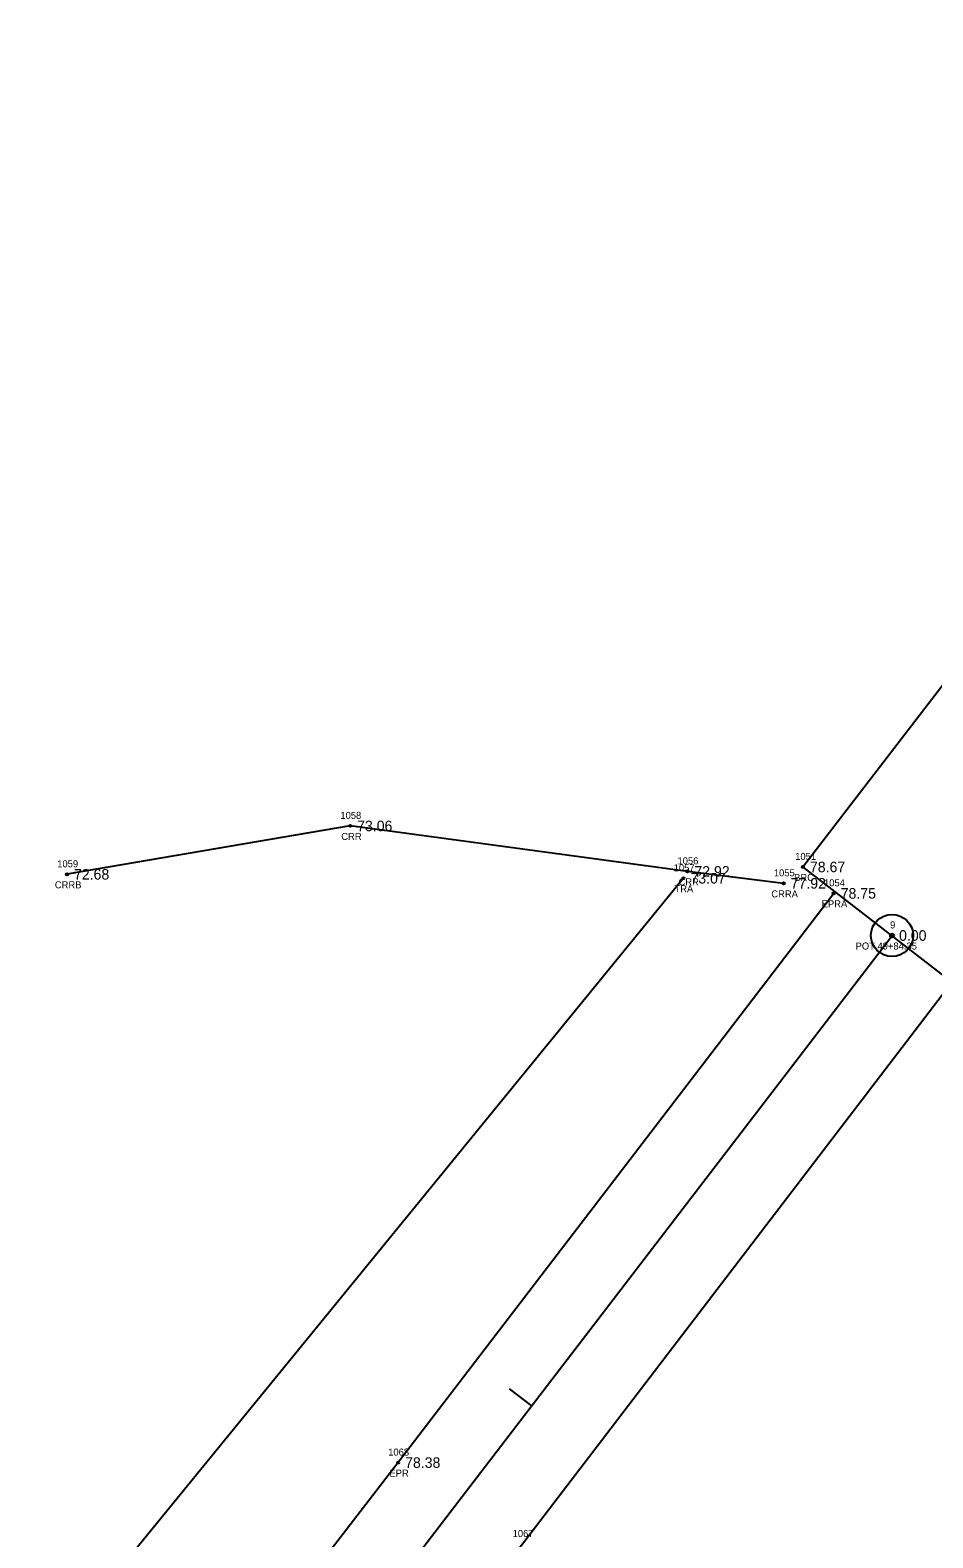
# Model space of a CAD drawing. Extents: x 2505249 to 2506333, y 912937 to 914171.
# Drawn here: x 2505909.6 to 2506038.1, y 913721.3 to 913936 of the extents above; entities that cross this region are included whole.
import ezdxf

# ---------------------------------------------------------------- set-up
doc = ezdxf.new("R2010")
doc.units = 0
for name, color, linetype in [('RD_EX_Bridge', 7, 'Continuous'), ('RD_EX_Bridge_txCode', 7, 'Continuous'), ('RD_EX_H2O', 7, 'Continuous'), ('RD_EX_H2O_txCode', 7, 'Continuous'), ('RD_EX_Road', 7, 'Continuous'), ('RD_EX_Road_txCode', 7, 'Continuous'), ('RD_EX_TX_Bridge_ELEV', 7, 'Continuous'), ('RD_EX_TX_H2O_ELEV', 7, 'Continuous'), ('RD_EX_TX_Road_ELEV', 7, 'Continuous'), ('RD_EX_TX_VEG_ELEV', 7, 'Continuous'), ('RD_EX_VEG', 7, 'Continuous'), ('RD_EX_VEG_txCode', 7, 'Continuous'), ('RD_HC_Cl', 7, 'Continuous'), ('RD_HC_Data', 7, 'Continuous'), ('RD_HC_Data_Tic', 7, 'Continuous'), ('RD_HC_Survey_ELEV', 7, 'Continuous'), ('RD_HC_txCode', 7, 'Continuous'), ('RD_SMD_Locator', 7, 'Continuous')]:
    doc.layers.add(name, color=color, linetype=linetype)

msp = doc.modelspace()

# ---------------------------------------------------------------- linework, layer by layer
at = {"layer": 'RD_EX_Bridge'}
msp.add_lwpolyline([(2506111.24, 913935.99), (2506135.76, 913916.92), (2506044.08, 913798.01), (2506019.65, 913816.86), (2506111.24, 913935.99)], dxfattribs=at)
at = {"layer": 'RD_EX_H2O'}
msp.add_lwpolyline([(2506016.9, 913814.52), (2506003.2, 913816.23), (2505955.18, 913822.7), (2505914.87, 913815.81)], dxfattribs=at)
at = {"layer": 'RD_EX_Road'}
for points in [[(2506024.03, 913813.1), (2505962.01, 913732.06), (2505903.3, 913655.93), (2505840.88, 913574.4), (2505819.41, 913546.54), (2505814.19, 913542.64)], [(2506040.71, 913800.23), (2505979.73, 913720.47), (2505920.44, 913642.61), (2505859.42, 913562.61), (2505835.44, 913531.43), (2505833.77, 913527.25)]]:
    msp.add_lwpolyline(points, dxfattribs=at)
at = {"layer": 'RD_EX_VEG'}
msp.add_lwpolyline([(2506002.64, 913815.25), (2505883.7, 913669.64), (2505827.83, 913593.29), (2505814.43, 913589.15), (2505792.49, 913560.55), (2505725.64, 913468.24), (2505664.37, 913399.09), (2505478.33, 913221), (2505411.99, 913152.19), (2505339.13, 913074.53)], dxfattribs=at)
at = {"layer": 'RD_HC_Cl'}
msp.add_line((2505792.76, 913494.51), (2506032.34, 913807.1), dxfattribs=at)
at = {"layer": 'RD_HC_Data'}
for radius in [3, 0.282]:
    msp.add_circle((2506032.34, 913807.1), radius, dxfattribs=at)
at = {"layer": 'RD_HC_Data_Tic'}
msp.add_line((2505981.03, 913740.15), (2505977.86, 913742.58), dxfattribs=at)
at = {"layer": 'RD_SMD_Locator'}
for centre in [(2505955.18, 913822.7), (2506003.2, 913816.23), (2506019.65, 913816.86), (2505914.87, 913815.81), (2506002.64, 913815.25), (2506016.9, 913814.52), (2506024.03, 913813.1), (2506032.34, 913807.1), (2505962.01, 913732.06)]:
    msp.add_circle(centre, 0.15, dxfattribs=at)

# ---------------------------------------------------------------- texts
at = {"layer": 'RD_EX_Bridge_txCode'}
for s, p in [('1051', (2506018.55, 913817.86)), ('BRC', (2506018.4, 913814.86))]:
    msp.add_text(s, height=1, dxfattribs=at).set_placement(p)
at = {"layer": 'RD_EX_H2O_txCode'}
for s, p in [('1058', (2505953.79, 913823.7)), ('CRR', (2505953.92, 913820.7)), ('1059', (2505913.48, 913816.81)), ('1056', (2506001.79, 913817.23)), ('1055', (2506015.51, 913815.52)), ('CRRB', (2505913.14, 913813.81)), ('CRR', (2506001.94, 913814.23)), ('CRRA', (2506015.15, 913812.52))]:
    msp.add_text(s, height=1, dxfattribs=at).set_placement(p)
at = {"layer": 'RD_EX_Road_txCode'}
for s, p in [('1054', (2506022.65, 913814.1)), ('EPRA', (2506022.32, 913811.1)), ('1068', (2505960.6, 913733.06)), ('EPR', (2505960.78, 913730.06)), ('1067', (2505978.32, 913721.47))]:
    msp.add_text(s, height=1, dxfattribs=at).set_placement(p)
at = {"layer": 'RD_EX_TX_Bridge_ELEV'}
msp.add_text('78.67', height=1.5, dxfattribs=at).set_placement((2506020.65, 913816.11))
at = {"layer": 'RD_EX_TX_H2O_ELEV'}
for s, p in [('73.06', (2505956.18, 913821.95)), ('72.68', (2505915.87, 913815.06)), ('72.92', (2506004.2, 913815.48)), ('77.92', (2506017.9, 913813.77))]:
    msp.add_text(s, height=1.5, dxfattribs=at).set_placement(p)
at = {"layer": 'RD_EX_TX_Road_ELEV'}
for s, p in [('78.75', (2506025.03, 913812.35)), ('78.38', (2505963.01, 913731.31))]:
    msp.add_text(s, height=1.5, dxfattribs=at).set_placement(p)
at = {"layer": 'RD_EX_TX_VEG_ELEV'}
msp.add_text('73.07', height=1.5, dxfattribs=at).set_placement((2506003.64, 913814.5))
at = {"layer": 'RD_EX_VEG_txCode'}
for s, p in [('1057', (2506001.25, 913816.25)), ('TRA', (2506001.36, 913813.25))]:
    msp.add_text(s, height=1, dxfattribs=at).set_placement(p)
at = {"layer": 'RD_HC_Survey_ELEV'}
msp.add_text('0.00', height=1.5, dxfattribs=at).set_placement((2506033.34, 913806.35))
at = {"layer": 'RD_HC_txCode'}
for s, p in [('9', (2506032.06, 913808.1)), ('POT 49+84.35', (2506027.15, 913805.1))]:
    msp.add_text(s, height=1, dxfattribs=at).set_placement(p)

doc.saveas('drawing.dxf')
